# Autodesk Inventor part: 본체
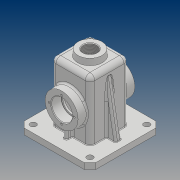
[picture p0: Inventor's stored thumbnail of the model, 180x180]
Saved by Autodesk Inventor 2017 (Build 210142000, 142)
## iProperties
Part Number: 본체
Material: 일반
Document SubType Name: Modeling
Designer: 20
Density: 1 g/cm^3
Appearance: 기본값
Mass: 293.011 g
Surface Area: 899.149 cm^2
Volume: 293.011 cm^3
Author: 20
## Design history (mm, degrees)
sketch "스케치2"
  geometry: L1 (-32.5, -32.5)-(32.5, -32.5); L2 (32.5, -32.5)-(32.5, 32.5); L3 (32.5, 32.5)-(-32.5, 32.5); L4 (-32.5, 32.5)-(-32.5, -32.5); L5 (-32.5, -32.5)-(32.5, 32.5); L6 (32.5, -32.5)-(-32.5, 32.5); 1 further point
  constraints: 12 end point, 2 midpoint, 2 parallel, 1 horizontal, 1 perpendicular
  dimensions: "d2" = 65 distance of L2.end L3.end; "d3" = 65 distance of L1.end L2.end
extrude "돌출1" new body sketch "스케치2" distance "d4" = 110; taper "d5" = 0 deg
feature "쉘1" dims "d8" = 5
sketch "스케치3"
  geometry: L1 (60, -60)-(-60, -60); L2 (-60, -60)-(-60, 60); L3 (-60, 60)-(60, 60); L4 (60, 60)-(60, -60); L5 (60, -60)-(-60, 60); L6 (-60, -60)-(60, 60); L7 (-32.5, -32.5)-(-32.5, 32.5) reference; L8 (32.5, -32.5)-(-32.5, -32.5) reference; L9 (32.5, 32.5)-(32.5, -32.5) reference; L10 (-32.5, 32.5)-(32.5, 32.5) reference; A1 r 8 centre (-24.5, -24.5) between (-32.5, -24.5) and (-24.5, -32.5) reference; A2 r 8 centre (24.5, -24.5) between (24.5, -32.5) and (32.5, -24.5) reference; A3 r 8 centre (24.5, 24.5) between (32.5, 24.5) and (24.5, 32.5) reference; A4 r 8 centre (-24.5, 24.5) between (-24.5, 32.5) and (-32.5, 24.5) reference; 1 further point
  constraints: 12 end point, 2 midpoint, 2 parallel, 1 horizontal, 1 perpendicular
  dimensions: "d9" = 120 distance of L1.end L2.end; "d10" = 120 distance of L2.end L3.end
extrude "돌출2" join sketch "스케치3" distance "d11" = 10; taper "d12" = 0 deg
chamfer "모따기1" distance "d13" = 10; stored, may be unused: second distance "d14" = 2, angle "d15" = 45 deg
sketch "스케치10"
  geometry: L1 (-48, 10)-(-41.988, 44.095); L2 (50, 10)-(-50, 10) reference; L3 (-60, 0)-(-60, 10) reference; 1 further point
  constraints: 2 end point, 1 point on line
  dimensions: "d37" = 10 deg angle of L3 L1; "d38" = 12 distance from line of L3 L1.start; "d39" = 34.095 vertical distance of L1.start L1.end
feature "리브1" sketch "스케치10" dims "d40" = 1, "d41" = 10, "d42" = 0, "d43" = 0, "d44" = 1, "d45" = 1
sketch "스케치13"
  geometry: C1 r 20 at (0, 0); 1 further point
  constraints: 1 centre point, 1 coincident
  dimensions: "d57" = 40 diameter of C1
extrude "돌출9" join sketch "스케치13" distance "d58" = 10; taper "d59" = 0 deg
sketch "스케치14"
  geometry: 2 further points
  constraints: 1 coincident
hole "구멍1" sketch "스케치14" at (0, 0) diameter "d60" = 22.835; stored, may be unused: countersink angle "d64" = 90 deg, drill point angle "d66" = 118 deg; dims "d61" = 50, "d62" = 4, "d63" = 2, "d65" = 59.3
feature "면 기울기1" dims angle "d67" = 5 deg
fillet "모깎기4" dims "d91" = 8
fillet "모깎기5" dims "d92" = 3
fillet "모깎기6" dims "d93" = 3
fillet "모깎기7" dims "d94" = 3
sketch "스케치18"
  geometry: L1 (-17.5, -10)-(82.5, -10) reference; C1 r 27.5 at (32.5, 45); 2 further points
  constraints: 1 centre point, 1 midpoint, 1 vertical alignment
  dimensions: "d97" = 55 diameter of C1; "d98" = 55 distance from line of L1 C1.centre
extrude "돌출10" join sketch "스케치18" distance "d99" = 15; taper "d100" = 0 deg
sketch "스케치19"
  geometry: C1 r 15 at (0, 0); C2 r 27.5 at (0, 0) reference; 1 further point
  constraints: 1 centre point, 1 concentric
  dimensions: "d101" = 30 diameter of C1
extrude "돌출11" cut sketch "스케치19" stored distance "d102" = 15; taper "d103" = 0 deg
sketch "스케치20"
  geometry: C1 r 17.5 at (0, 0); C2 r 27.5 at (0, 0) reference; 1 further point
  constraints: 1 centre point, 1 concentric
  dimensions: "d104" = 35 diameter of C1
extrude "돌출12" cut sketch "스케치20" distance "d105" = 17; taper "d106" = 0 deg
sketch "스케치21" dims "d107" = 42
  geometry: C1 r 27.5 at (0, 0) reference; 3 further points
  constraints: 2 vertical alignment, 3 other
hole "구멍4" sketch "스케치21" at (0, 21) diameter "d108" = 3.242; stored, may be unused: countersink angle "d112" = 90 deg, drill point angle "d114" = 118 deg; dims "d109" = 8, "d110" = 4, "d111" = 2, "d113" = 10
sketch "스케치22"
  geometry: L1 (-42.5, 10)-(-42.5, 23.754); L2 (50, 10)-(-50, 10) reference; L3 (-27.5, 102)-(-27.5, 0) reference; 1 further point
  constraints: 2 end point, 1 point on line
  dimensions: "d119" = 15 distance between parallel lines of L3 L1; "d122" = 13.7535 distance of L1.start L1.end; "d123" = 90 deg angle of L2 L1 (derived)
feature "리브3" sketch "스케치22" dims "d124" = 1, "d125" = 6, "d126" = 0, "d127" = 0, "d128" = 1, "d129" = 1
fillet "모깎기8" dims "d130" = 8
fillet "모깎기15" dims "d137" = 3
fillet "모깎기16" dims "d138" = 3
fillet "모깎기17" dims "d139" = 3
fillet "모깎기21" dims "d143" = 3
fillet "모깎기22" dims "d144" = 3
fillet "모깎기23" dims "d145" = 3
fillet "모깎기24" dims "d146" = 1
chamfer "모따기2" distance "d147" = 1; stored, may be unused: second distance "d148" = 2, angle "d149" = 45 deg
sketch "스케치23"
  geometry: C1 r 5 at (-47.5, -47.5); 1 further point
  constraints: 1 centre point
  dimensions: "d150" = 10 diameter of C1; "d151" = 47.5 horizontal distance of C1.centre point (0, 0); "d152" = 47.5 horizontal distance of point (0, 0) C1.centre
extrude "돌출13" cut sketch "스케치23" distance "d153" = 10; taper "d154" = 0 deg
chamfer "모따기3" distance "d161" = 1; stored, may be unused: second distance "d162" = 2, angle "d163" = 45 deg
node "작업 평면1"
sketch "스케치26"
  geometry: L1 (-20, -65)-(20, -65) reference; L2 (32.5, -47)-(32.5, 44) reference; 2 further points
  constraints: 1 other
  dimensions: "d165" = 26 distance from line of L1 point (0, -39); "d166" = 32.5 distance from line of L2 point (0, -39)
feature "엠보싱1" sketch "스케치26" dims "d167" = 0.5, "d168" = 0
fillet "모깎기25" dims "d169" = 3
fillet "모깎기26" dims "d170" = 0.3
sketch "스케치27"
  geometry: 1 further point
node "솔리드1"
mirror "미러1"
pattern_circular "원형 패턴3" dims angle "d116" = 360 deg
mirror "미러3"
mirror "미러4"
pattern_linear "직사각형 패턴1" dims "d157" = 95, "d160" = 95
other parameters: "d164" = 44
